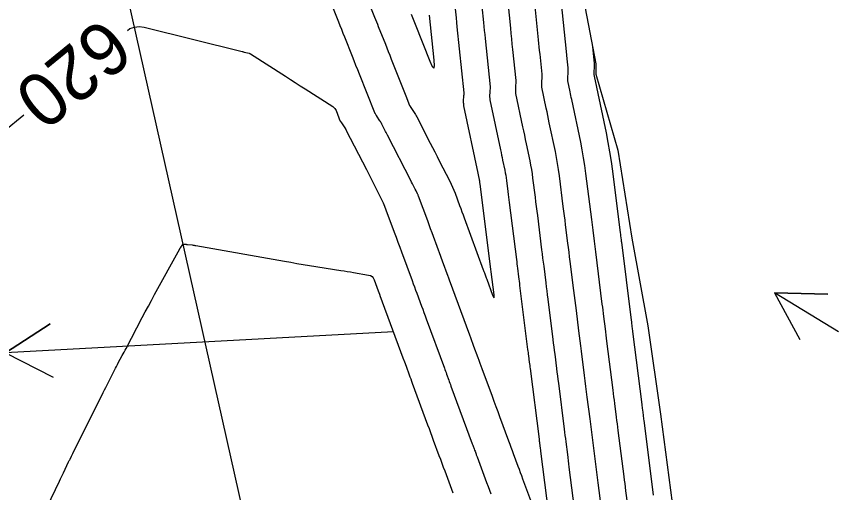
# Model space of a CAD drawing. Extents: x 954385 to 988206, y 1868364 to 1924553.
# Drawn here: x 958114.8 to 958207.1, y 1918400.9 to 1918454.4 of the extents above; entities that cross this region are included whole.
import ezdxf

# ---------------------------------------------------------------- set-up
doc = ezdxf.new("R2010")
doc.units = 0
for name, color, linetype in [('24', 7, 'Continuous'), ('26', 7, 'Continuous'), ('5', 7, 'Continuous'), ('6', 7, 'Continuous'), ('7', 7, 'Continuous'), ('Default', 7, 'Continuous')]:
    doc.layers.add(name, color=color, linetype=linetype)

msp = doc.modelspace()

# ---------------------------------------------------------------- linework, layer by layer
at = {"layer": '24'}
msp.add_lwpolyline([(958166.174, 1918538.226), (958167.505, 1918528.276), (958168.873, 1918518.334), (958170.656, 1918508.486), (958172.595, 1918498.672), (958174.126, 1918488.767), (958175.694, 1918478.87), (958176.714, 1918468.85), (958177.967, 1918458.883), (958179.861, 1918449.059), (958179.867, 1918447.902), (958182.315, 1918439.361), (958183.913, 1918429.471), (958185.71, 1918419.626), (958187.127, 1918409.695), (958188.425, 1918399.738), (958190.025, 1918389.848), (958192.011, 1918380.045), (958194.127, 1918370.271), (958196.146, 1918360.475), (958197.733, 1918350.583), (958199.858, 1918340.811)], dxfattribs=at)
at = {"layer": '26'}
for points in [[(958207.131, 1918418.928), (958199.924, 1918423.336), (958205.922, 1918423.184), (958199.924, 1918423.336), (958202.791, 1918418.066)], [(958157.131, 1918418.928), (958113.53, 1918416.575), (958118.557, 1918419.851), (958113.53, 1918416.575), (958118.88, 1918413.859)]]:
    msp.add_lwpolyline(points, dxfattribs=at)
at = {"layer": '6'}
for points in [[(958177.618, 1918397.909), (958176.876, 1918403.746), (958176.831, 1918404.101), (958176.786, 1918404.456), (958176.741, 1918404.81), (958176.696, 1918405.165), (958176.516, 1918406.584), (958176.471, 1918406.938), (958176.426, 1918407.293), (958176.381, 1918407.648), (958176.336, 1918408.003), (958175.683, 1918413.17), (958175.632, 1918413.579), (958175.58, 1918413.988), (958175.528, 1918414.397), (958175.477, 1918414.806), (958175.271, 1918416.442), (958175.219, 1918416.851), (958175.168, 1918417.26), (958175.116, 1918417.669), (958175.065, 1918418.078), (958174.496, 1918422.618), (958174.439, 1918423.079), (958174.381, 1918423.54), (958174.323, 1918424.001), (958174.265, 1918424.462), (958174.034, 1918426.306), (958173.976, 1918426.767), (958173.919, 1918427.228), (958173.861, 1918427.689), (958173.803, 1918428.15), (958173.322, 1918431.998), (958173.256, 1918432.518), (958173.191, 1918433.038), (958173.126, 1918433.558), (958173.061, 1918434.077), (958172.791, 1918436.223), (958172.725, 1918436.709), (958172.649, 1918437.193), (958172.563, 1918437.675), (958172.467, 1918438.156), (958172.064, 1918440.075), (958171.963, 1918440.555), (958171.862, 1918441.035), (958171.761, 1918441.515), (958171.66, 1918441.994), (958170.874, 1918445.729), (958170.861, 1918445.803), (958170.853, 1918445.878), (958170.849, 1918445.953), (958170.851, 1918446.028), (958170.868, 1918446.34), (958170.872, 1918446.411), (958170.875, 1918446.482), (958170.879, 1918446.553), (958170.883, 1918446.624), (958170.899, 1918446.908), (958170.901, 1918446.979), (958170.901, 1918447.05), (958170.898, 1918447.12), (958170.892, 1918447.191), (958170.535, 1918450.669), (958170.473, 1918451.272), (958170.411, 1918451.876), (958170.349, 1918452.479), (958170.288, 1918453.082), (958169.989, 1918455.996)], [(958127.216, 1918452.819), (958127.51, 1918453.011), (958128.012, 1918453.192), (958128.544, 1918453.243), (958129.104, 1918453.165), (958140.098, 1918450.441), (958140.158, 1918450.426), (958140.217, 1918450.412), (958140.276, 1918450.397), (958140.335, 1918450.382), (958140.906, 1918450.238), (958140.941, 1918450.228), (958140.975, 1918450.215), (958141.008, 1918450.199), (958141.04, 1918450.18), (958144.969, 1918447.664), (958145.528, 1918447.306), (958146.086, 1918446.948), (958146.645, 1918446.591), (958147.203, 1918446.233), (958150.291, 1918444.255), (958150.413, 1918444.163), (958150.516, 1918444.056), (958150.601, 1918443.934), (958150.668, 1918443.797), (958150.982, 1918443.007), (958151.029, 1918442.889), (958151.107, 1918442.692), (958151.123, 1918442.653), (958151.142, 1918442.615), (958151.162, 1918442.578), (958151.185, 1918442.543), (958151.713, 1918441.741), (958151.74, 1918441.7), (958151.785, 1918441.632), (958151.793, 1918441.618), (958151.802, 1918441.604), (958151.81, 1918441.59), (958151.817, 1918441.576), (958154.071, 1918437.173), (958154.261, 1918436.801), (958154.452, 1918436.429), (958154.643, 1918436.056), (958154.833, 1918435.684), (958155.596, 1918434.195), (958155.781, 1918433.821), (958155.954, 1918433.441), (958156.116, 1918433.056), (958156.266, 1918432.667), (958157.202, 1918430.132), (958157.406, 1918429.579), (958157.61, 1918429.026), (958157.815, 1918428.473), (958158.019, 1918427.92), (958159.206, 1918424.706), (958159.339, 1918424.346), (958159.472, 1918423.986), (958159.605, 1918423.627), (958159.737, 1918423.267), (958160.268, 1918421.828), (958160.4, 1918421.468), (958160.533, 1918421.109), (958160.666, 1918420.749), (958160.798, 1918420.389), (958162.838, 1918414.855), (958162.9, 1918414.688), (958162.962, 1918414.521), (958163.023, 1918414.353), (958163.085, 1918414.186), (958163.332, 1918413.517), (958163.394, 1918413.349), (958163.456, 1918413.182), (958163.517, 1918413.014), (958163.579, 1918412.847), (958165.975, 1918406.353), (958166.026, 1918406.214), (958166.078, 1918406.074), (958166.181, 1918405.795), (958166.232, 1918405.655), (958166.284, 1918405.515), (958166.398, 1918405.206), (958166.425, 1918405.131), (958166.453, 1918405.056), (958166.481, 1918404.981), (958166.508, 1918404.906), (958167.587, 1918401.99), (958167.743, 1918401.57), (958167.898, 1918401.149), (958168.053, 1918400.729)], [(958113.284, 1918441.448), (958115.588, 1918443.343)]]:
    msp.add_lwpolyline(points, dxfattribs=at)
at = {"layer": '7'}
for points in [[(958153.529, 1918457.983), (958154.999, 1918454.296), (958155.103, 1918454.036), (958155.207, 1918453.775), (958155.311, 1918453.514), (958155.415, 1918453.254), (958156.204, 1918451.268), (958156.37, 1918450.85), (958156.536, 1918450.432), (958156.702, 1918450.014), (958156.868, 1918449.596), (958158.213, 1918446.207), (958158.286, 1918446.023), (958158.359, 1918445.839), (958158.432, 1918445.654), (958158.505, 1918445.47), (958158.936, 1918444.386), (958158.94, 1918444.376), (958158.945, 1918444.366), (958158.95, 1918444.356), (958158.956, 1918444.347), (958158.992, 1918444.292), (958159.004, 1918444.273), (958159.454, 1918443.59), (958159.53, 1918443.472), (958159.602, 1918443.352), (958159.67, 1918443.23), (958159.736, 1918443.107), (958161.253, 1918440.142), (958161.506, 1918439.648), (958161.759, 1918439.154), (958162.012, 1918438.66), (958162.265, 1918438.166), (958163.447, 1918435.859), (958163.61, 1918435.528), (958163.763, 1918435.194), (958163.906, 1918434.854), (958164.038, 1918434.511), (958164.549, 1918433.127), (958164.677, 1918432.782), (958164.804, 1918432.436), (958164.932, 1918432.09), (958165.06, 1918431.744), (958167.212, 1918425.917), (958167.245, 1918425.828), (958167.278, 1918425.738), (958167.311, 1918425.649), (958167.344, 1918425.56), (958167.541, 1918425.024), (958167.607, 1918424.845), (958168.261, 1918423.071), (958168.361, 1918422.829), (958168.42, 1918422.754), (958168.438, 1918422.847), (958168.415, 1918423.108), (958168.092, 1918425.689), (958168.057, 1918425.965), (958166.934, 1918434.938), (958166.922, 1918435.033), (958166.91, 1918435.127), (958166.899, 1918435.222), (958166.887, 1918435.316), (958166.838, 1918435.706), (958166.826, 1918435.794), (958166.812, 1918435.882), (958166.796, 1918435.97), (958166.779, 1918436.057), (958166.706, 1918436.406), (958166.669, 1918436.58), (958166.632, 1918436.754), (958165.04, 1918444.319), (958165.018, 1918444.442), (958165.005, 1918444.565), (958164.999, 1918444.689), (958165.002, 1918444.813), (958165.04, 1918445.517), (958165.045, 1918445.605), (958165.05, 1918445.692), (958165.05, 1918445.714), (958165.05, 1918445.736), (958165.049, 1918445.758), (958165.047, 1918445.78), (958164.285, 1918453.208), (958164.233, 1918453.717), (958164.181, 1918454.226), (958164.076, 1918455.245)], [(958183.443, 1918399.453), (958183.237, 1918401.073), (958183.185, 1918401.478), (958183.134, 1918401.883), (958183.083, 1918402.288), (958183.031, 1918402.693), (958182.376, 1918407.849), (958182.328, 1918408.228), (958182.28, 1918408.607), (958182.232, 1918408.986), (958182.184, 1918409.365), (958181.992, 1918410.881), (958181.945, 1918411.26), (958181.897, 1918411.639), (958181.849, 1918412.018), (958181.801, 1918412.398), (958181.111, 1918417.876), (958181.067, 1918418.225), (958181.023, 1918418.574), (958180.979, 1918418.923), (958180.935, 1918419.272), (958180.761, 1918420.668), (958180.717, 1918421.017), (958180.673, 1918421.366), (958180.629, 1918421.715), (958180.586, 1918422.064), (958179.849, 1918427.941), (958179.811, 1918428.241), (958179.774, 1918428.542), (958179.736, 1918428.843), (958179.698, 1918429.144), (958179.548, 1918430.347), (958179.51, 1918430.647), (958179.472, 1918430.948), (958179.435, 1918431.249), (958179.397, 1918431.55), (958178.744, 1918436.741), (958178.624, 1918437.624), (958178.486, 1918438.504), (958178.33, 1918439.381), (958178.155, 1918440.255), (958177.144, 1918445.064), (958177.1, 1918445.277), (958177.055, 1918445.49), (958177.01, 1918445.702), (958176.965, 1918445.915), (958176.708, 1918447.139), (958176.703, 1918447.165), (958176.7, 1918447.191), (958176.699, 1918447.217), (958176.7, 1918447.244), (958176.707, 1918447.377), (958176.711, 1918447.456), (958176.748, 1918448.123), (958176.752, 1918448.243), (958176.752, 1918448.363), (958176.746, 1918448.483), (958176.736, 1918448.603), (958176.632, 1918449.616), (958176.59, 1918450.034), (958176.547, 1918450.452), (958175.764, 1918458.086)], [(958180.48, 1918399.077), (958180.112, 1918401.974), (958180.036, 1918402.572), (958179.96, 1918403.169), (958179.884, 1918403.767), (958179.808, 1918404.364), (958179.504, 1918406.755), (958179.429, 1918407.353), (958179.353, 1918407.95), (958179.277, 1918408.548), (958179.202, 1918409.145), (958178.892, 1918411.598), (958178.815, 1918412.206), (958178.738, 1918412.814), (958178.662, 1918413.422), (958178.585, 1918414.03), (958178.238, 1918416.783), (958178.167, 1918417.35), (958178.095, 1918417.917), (958178.024, 1918418.484), (958177.953, 1918419.051), (958177.669, 1918421.319), (958177.598, 1918421.886), (958177.527, 1918422.453), (958177.456, 1918423.02), (958177.385, 1918423.587), (958176.975, 1918426.858), (958176.91, 1918427.372), (958176.846, 1918427.885), (958176.782, 1918428.399), (958176.718, 1918428.912), (958176.46, 1918430.966), (958176.396, 1918431.479), (958176.332, 1918431.993), (958176.267, 1918432.506), (958176.203, 1918433.02), (958175.768, 1918436.482), (958175.675, 1918437.166), (958175.567, 1918437.848), (958175.446, 1918438.528), (958175.311, 1918439.205), (958174.63, 1918442.444), (958174.544, 1918442.853), (958174.458, 1918443.262), (958174.372, 1918443.671), (958174.286, 1918444.08), (958173.791, 1918446.434), (958173.782, 1918446.484), (958173.776, 1918446.534), (958173.774, 1918446.585), (958173.775, 1918446.636), (958173.786, 1918446.84), (958173.792, 1918446.943), (958173.798, 1918447.045), (958173.823, 1918447.516), (958173.827, 1918447.611), (958173.826, 1918447.706), (958173.822, 1918447.802), (958173.814, 1918447.897), (958173.584, 1918450.143), (958173.542, 1918450.549), (958173.5, 1918450.955), (958173.459, 1918451.361), (958173.417, 1918451.767), (958172.876, 1918457.041)], [(958173.779, 1918396.679), (958171.665, 1918402.393), (958171.535, 1918402.747), (958171.404, 1918403.101), (958171.273, 1918403.455), (958171.142, 1918403.808), (958170.618, 1918405.224), (958170.487, 1918405.578), (958170.357, 1918405.931), (958170.226, 1918406.285), (958170.095, 1918406.639), (958169.085, 1918409.377), (958168.873, 1918409.951), (958168.662, 1918410.525), (958168.45, 1918411.099), (958168.238, 1918411.673), (958167.097, 1918414.763), (958166.98, 1918415.08), (958166.863, 1918415.396), (958166.746, 1918415.713), (958166.629, 1918416.03), (958166.162, 1918417.298), (958166.045, 1918417.615), (958165.928, 1918417.932), (958165.811, 1918418.249), (958165.695, 1918418.566), (958163.417, 1918424.745), (958163.374, 1918424.862), (958163.331, 1918424.979), (958163.223, 1918425.271), (958163.158, 1918425.446), (958162.742, 1918426.573), (958162.666, 1918426.78), (958162.589, 1918426.987), (958162.513, 1918427.194), (958162.436, 1918427.402), (958161.612, 1918429.637), (958161.449, 1918430.079), (958161.286, 1918430.521), (958161.123, 1918430.962), (958160.96, 1918431.404), (958159.93, 1918434.191), (958159.904, 1918434.259), (958159.876, 1918434.325), (958159.846, 1918434.391), (958159.814, 1918434.456), (958159.649, 1918434.777), (958159.55, 1918434.97), (958159.252, 1918435.553), (958159.148, 1918435.756), (958159.096, 1918435.857), (958156.445, 1918441.033), (958156.371, 1918441.178), (958156.297, 1918441.323), (958156.223, 1918441.467), (958156.149, 1918441.612), (958155.807, 1918442.279), (958155.754, 1918442.379), (958155.699, 1918442.477), (958155.641, 1918442.574), (958155.581, 1918442.669), (958155.251, 1918443.172), (958155.23, 1918443.204), (958155.209, 1918443.236), (958155.188, 1918443.267), (958155.168, 1918443.299), (958155.084, 1918443.426), (958155.064, 1918443.458), (958155.045, 1918443.492), (958155.029, 1918443.526), (958155.014, 1918443.56), (958153.298, 1918447.878), (958153.099, 1918448.38), (958152.899, 1918448.882), (958152.7, 1918449.384), (958152.5, 1918449.887), (958151.64, 1918452.056), (958151.472, 1918452.478), (958151.304, 1918452.9), (958151.136, 1918453.322), (958150.968, 1918453.743), (958150.296, 1918455.43)], [(958167.044, 1918455.507), (958167.23, 1918453.7), (958167.276, 1918453.248), (958167.322, 1918452.796), (958167.369, 1918452.345), (958167.415, 1918451.893), (958167.97, 1918446.486), (958167.974, 1918446.439), (958167.976, 1918446.393), (958167.976, 1918446.347), (958167.974, 1918446.3), (958167.961, 1918446.068), (958167.956, 1918445.975), (958167.954, 1918445.928), (958167.926, 1918445.421), (958167.924, 1918445.321), (958167.929, 1918445.221), (958167.94, 1918445.122), (958167.957, 1918445.024), (958169.146, 1918439.374), (958169.206, 1918439.091), (958169.265, 1918438.807), (958169.325, 1918438.524), (958169.385, 1918438.24), (958169.623, 1918437.106), (958169.68, 1918436.822), (958169.73, 1918436.537), (958169.775, 1918436.251), (958169.814, 1918435.965), (958169.974, 1918434.697), (958170.012, 1918434.39), (958170.051, 1918434.082), (958170.089, 1918433.775), (958170.128, 1918433.468), (958170.93, 1918427.058), (958170.961, 1918426.814), (958170.991, 1918426.571), (958171.022, 1918426.328), (958171.052, 1918426.085), (958171.174, 1918425.113), (958171.204, 1918424.87), (958171.235, 1918424.627), (958171.265, 1918424.384), (958171.296, 1918424.141), (958172.195, 1918416.963), (958172.217, 1918416.783), (958172.24, 1918416.603), (958172.263, 1918416.423), (958172.285, 1918416.243), (958172.376, 1918415.522), (958172.399, 1918415.342), (958172.422, 1918415.162), (958172.444, 1918414.982), (958172.467, 1918414.802), (958173.47, 1918406.86), (958173.484, 1918406.748), (958173.499, 1918406.636), (958173.513, 1918406.524), (958173.527, 1918406.413), (958173.598, 1918405.854), (958173.626, 1918405.63), (958173.64, 1918405.519), (958174.757, 1918396.74)], [(958159.11, 1918454.651), (958159.339, 1918454.074), (958159.569, 1918453.497), (958161.211, 1918449.362), (958161.48, 1918448.766), (958161.646, 1918448.586), (958161.711, 1918448.823), (958161.674, 1918449.475), (958161.156, 1918454.523)], [(958179.483, 1918451.017), (958179.681, 1918449.09), (958179.686, 1918449.044), (958179.687, 1918449.032), (958179.687, 1918449.02), (958179.687, 1918449.009), (958179.687, 1918448.997), (958179.625, 1918447.864), (958179.624, 1918447.85), (958179.625, 1918447.843), (958179.658, 1918447.685), (958180.999, 1918441.304), (958181.213, 1918440.234), (958181.404, 1918439.159), (958181.574, 1918438.081), (958181.721, 1918436.999), (958182.591, 1918430.08), (958182.613, 1918429.904), (958182.635, 1918429.727), (958182.69, 1918429.287), (958182.712, 1918429.111), (958182.723, 1918429.023), (958183.786, 1918420.541), (958183.819, 1918420.279), (958183.852, 1918420.017), (958183.918, 1918419.493), (958183.934, 1918419.362), (958183.951, 1918419.231), (958183.967, 1918419.1), (958183.984, 1918418.969), (958185.017, 1918410.766), (958185.036, 1918410.615), (958185.055, 1918410.465), (958185.074, 1918410.315), (958185.093, 1918410.165), (958185.169, 1918409.564), (958185.188, 1918409.414), (958185.207, 1918409.264), (958185.226, 1918409.114), (958185.245, 1918408.964), (958186.267, 1918400.92), (958186.308, 1918400.596)], [(958116.819, 1918396.395), (958119.593, 1918402.173), (958119.703, 1918402.403), (958119.813, 1918402.633), (958119.924, 1918402.863), (958120.034, 1918403.094), (958120.618, 1918404.318), (958120.656, 1918404.397), (958120.694, 1918404.476), (958120.732, 1918404.554), (958120.77, 1918404.633), (958120.924, 1918404.948), (958120.962, 1918405.026), (958121.001, 1918405.105), (958121.04, 1918405.183), (958121.079, 1918405.261), (958124.507, 1918412.114), (958124.654, 1918412.408), (958124.801, 1918412.701), (958124.948, 1918412.995), (958125.095, 1918413.289), (958125.772, 1918414.639), (958125.876, 1918414.844), (958125.981, 1918415.048), (958126.088, 1918415.252), (958126.197, 1918415.454), (958126.635, 1918416.262), (958126.744, 1918416.465), (958126.852, 1918416.667), (958126.96, 1918416.87), (958127.067, 1918417.073), (958128.893, 1918420.546), (958129.234, 1918421.192), (958129.579, 1918421.836), (958129.926, 1918422.478), (958130.277, 1918423.119), (958133.109, 1918428.269), (958133.126, 1918428.297), (958133.142, 1918428.326), (958133.159, 1918428.354), (958133.177, 1918428.382), (958133.248, 1918428.494), (958133.266, 1918428.522), (958133.285, 1918428.549), (958133.303, 1918428.576), (958133.323, 1918428.603), (958133.432, 1918428.752), (958133.459, 1918428.781), (958133.49, 1918428.8), (958133.526, 1918428.809), (958133.565, 1918428.808), (958133.771, 1918428.779), (958133.819, 1918428.773), (958133.868, 1918428.766), (958133.916, 1918428.761), (958133.964, 1918428.755), (958134.497, 1918428.7), (958134.601, 1918428.688), (958134.706, 1918428.674), (958134.81, 1918428.658), (958134.914, 1918428.641), (958144.861, 1918426.881), (958145.566, 1918426.757), (958146.272, 1918426.637), (958146.979, 1918426.519), (958147.686, 1918426.405), (958151.213, 1918425.84), (958151.571, 1918425.782), (958151.928, 1918425.723), (958152.285, 1918425.664), (958152.642, 1918425.603), (958154.317, 1918425.316), (958154.531, 1918425.253), (958154.708, 1918425.145), (958154.846, 1918424.992), (958154.947, 1918424.793), (958155.405, 1918423.55), (958155.47, 1918423.374), (958155.552, 1918423.155), (958155.584, 1918423.067), (958155.6, 1918423.023), (958158.178, 1918416.031), (958158.354, 1918415.553), (958158.53, 1918415.076), (958158.882, 1918414.122), (958158.97, 1918413.883), (958159.058, 1918413.644), (958159.146, 1918413.406), (958159.234, 1918413.167), (958160.954, 1918408.506), (958161.114, 1918408.074), (958161.273, 1918407.641), (958161.433, 1918407.209), (958161.592, 1918406.776), (958162.231, 1918405.045), (958162.391, 1918404.613), (958162.55, 1918404.18), (958162.71, 1918403.748), (958162.87, 1918403.315), (958163.787, 1918400.837)]]:
    msp.add_lwpolyline(points, dxfattribs=at)
at = {"layer": 'Default'}
msp.add_line((958200.602, 1918129.717), (957843.865, 1919719.405), dxfattribs=at)

# ---------------------------------------------------------------- texts
at = {"layer": '5'}
msp.add_text('620', height=6, rotation=219.17685, dxfattribs=at).set_placement((958124.491, 1918454.468))

doc.saveas('drawing.dxf')
